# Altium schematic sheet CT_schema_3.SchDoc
size 287 x 169 mm
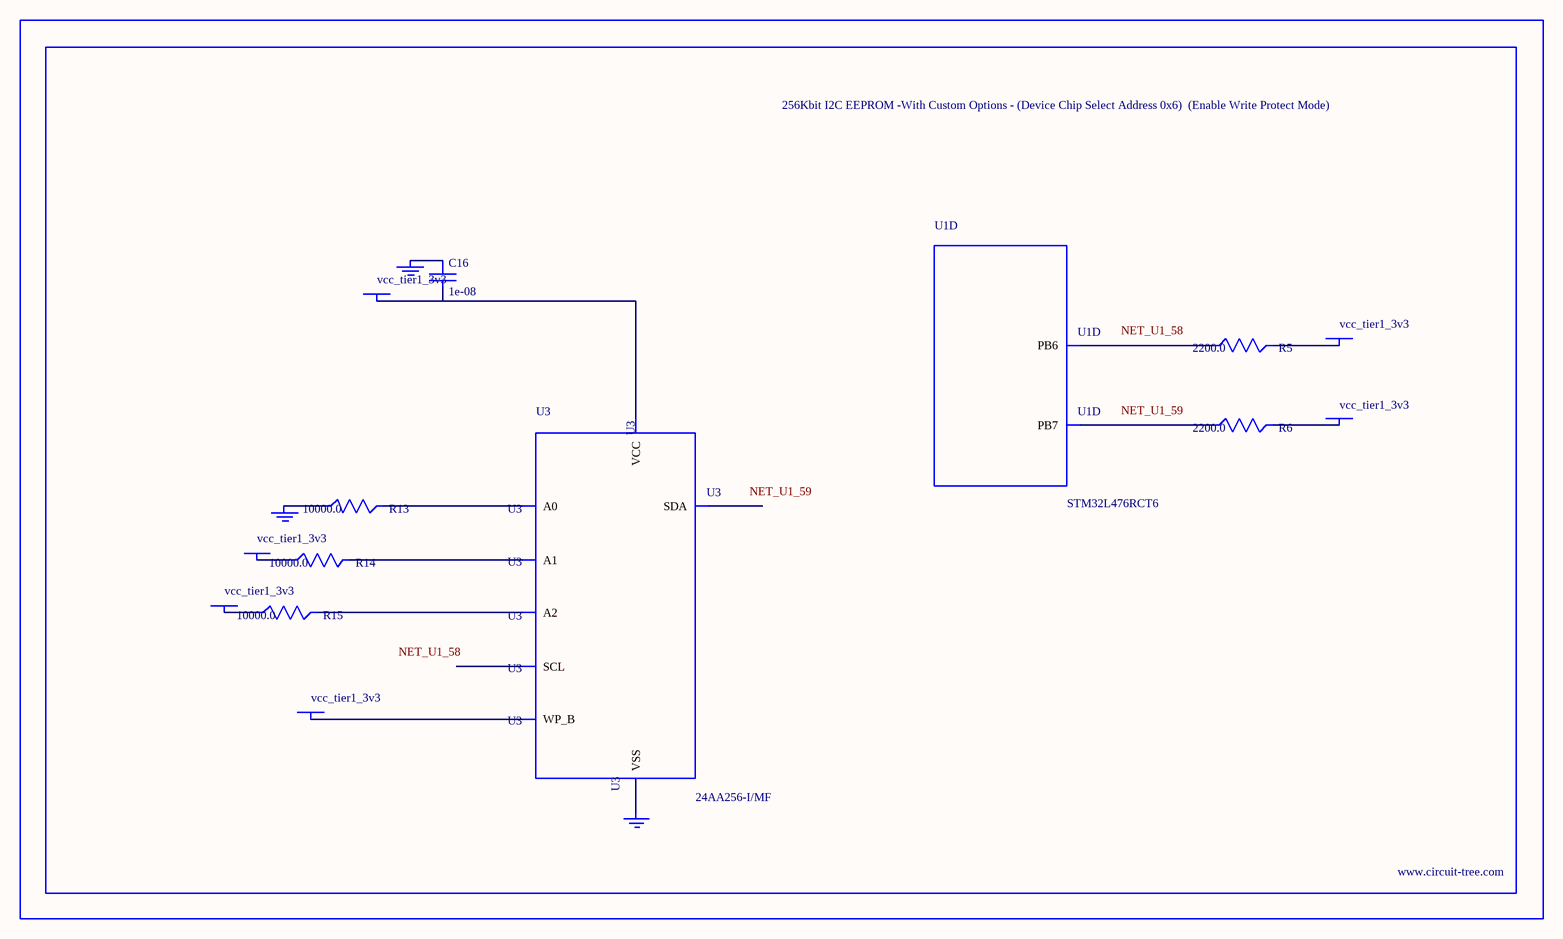
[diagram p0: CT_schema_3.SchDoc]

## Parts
BORDER2  (no value)
C16  1e-08  [C0402]
GND_INSTANCE_2_0  (no value)
GND_INSTANCE_2_1  (no value)
GND_INSTANCE_2_2  (no value)
POWER_INSTANCE_2_0  vcc_tier1_3v3
POWER_INSTANCE_2_1  vcc_tier1_3v3
POWER_INSTANCE_2_2  vcc_tier1_3v3
POWER_INSTANCE_2_3  vcc_tier1_3v3
POWER_INSTANCE_2_4  vcc_tier1_3v3
POWER_INSTANCE_2_5  vcc_tier1_3v3
R5  2200.0  [R0603]
R6  2200.0  [R0603]
R13  10000.0  [R0603]
R14  10000.0  [R0603]
R15  10000.0  [R0603]
U1  STM32L476RCT6  [LQFP64]  (part D of 6)
U3  24AA256-I/MF  [DFN8-S]

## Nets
NetC16_1: C16.1 GND_INSTANCE_2_1.0(GND)
NetC16_2: C16.2 POWER_INSTANCE_2_3.0(PWR) U3.8(VCC)
NetGND_INSTANCE_2_0_0: GND_INSTANCE_2_0.0(GND) R13.1
NetGND_INSTANCE_2_2_0: GND_INSTANCE_2_2.0(GND) U3.4(VSS)
NetPOWER_INSTANCE_2_0_0: POWER_INSTANCE_2_0.0(PWR) R14.1
NetPOWER_INSTANCE_2_1_0: POWER_INSTANCE_2_1.0(PWR) R15.1
NetPOWER_INSTANCE_2_2_0: POWER_INSTANCE_2_2.0(PWR) U3.7(WP_B)
NetPOWER_INSTANCE_2_4_0: POWER_INSTANCE_2_4.0(PWR) R5.2
NetPOWER_INSTANCE_2_5_0: POWER_INSTANCE_2_5.0(PWR) R6.2
NetR5_1: R5.1 U1.58(PB6)
NetR6_1: R6.1 U1.59(PB7)
NetR13_2: R13.2 U3.1(A0)
NetR14_2: R14.2 U3.2(A1)
NetR15_2: R15.2 U3.3(A2)

Not connected (* = marked no-connect by the designer): U3 5(SDA) 6(SCL)

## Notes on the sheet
- Labels drawn without touching a wire or pin: NET_U1_58, NET_U1_59

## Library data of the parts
BORDER2 = BORDER_PAGE2
C16 = C0402C103K3RAC
GND_INSTANCE_2_0-GND_INSTANCE_2_2 = GND
POWER_INSTANCE_2_0-POWER_INSTANCE_2_5 = PWR
R5 R6 = RC0603JR-072K2L
R13-R15 = RC0603JR-0710KL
